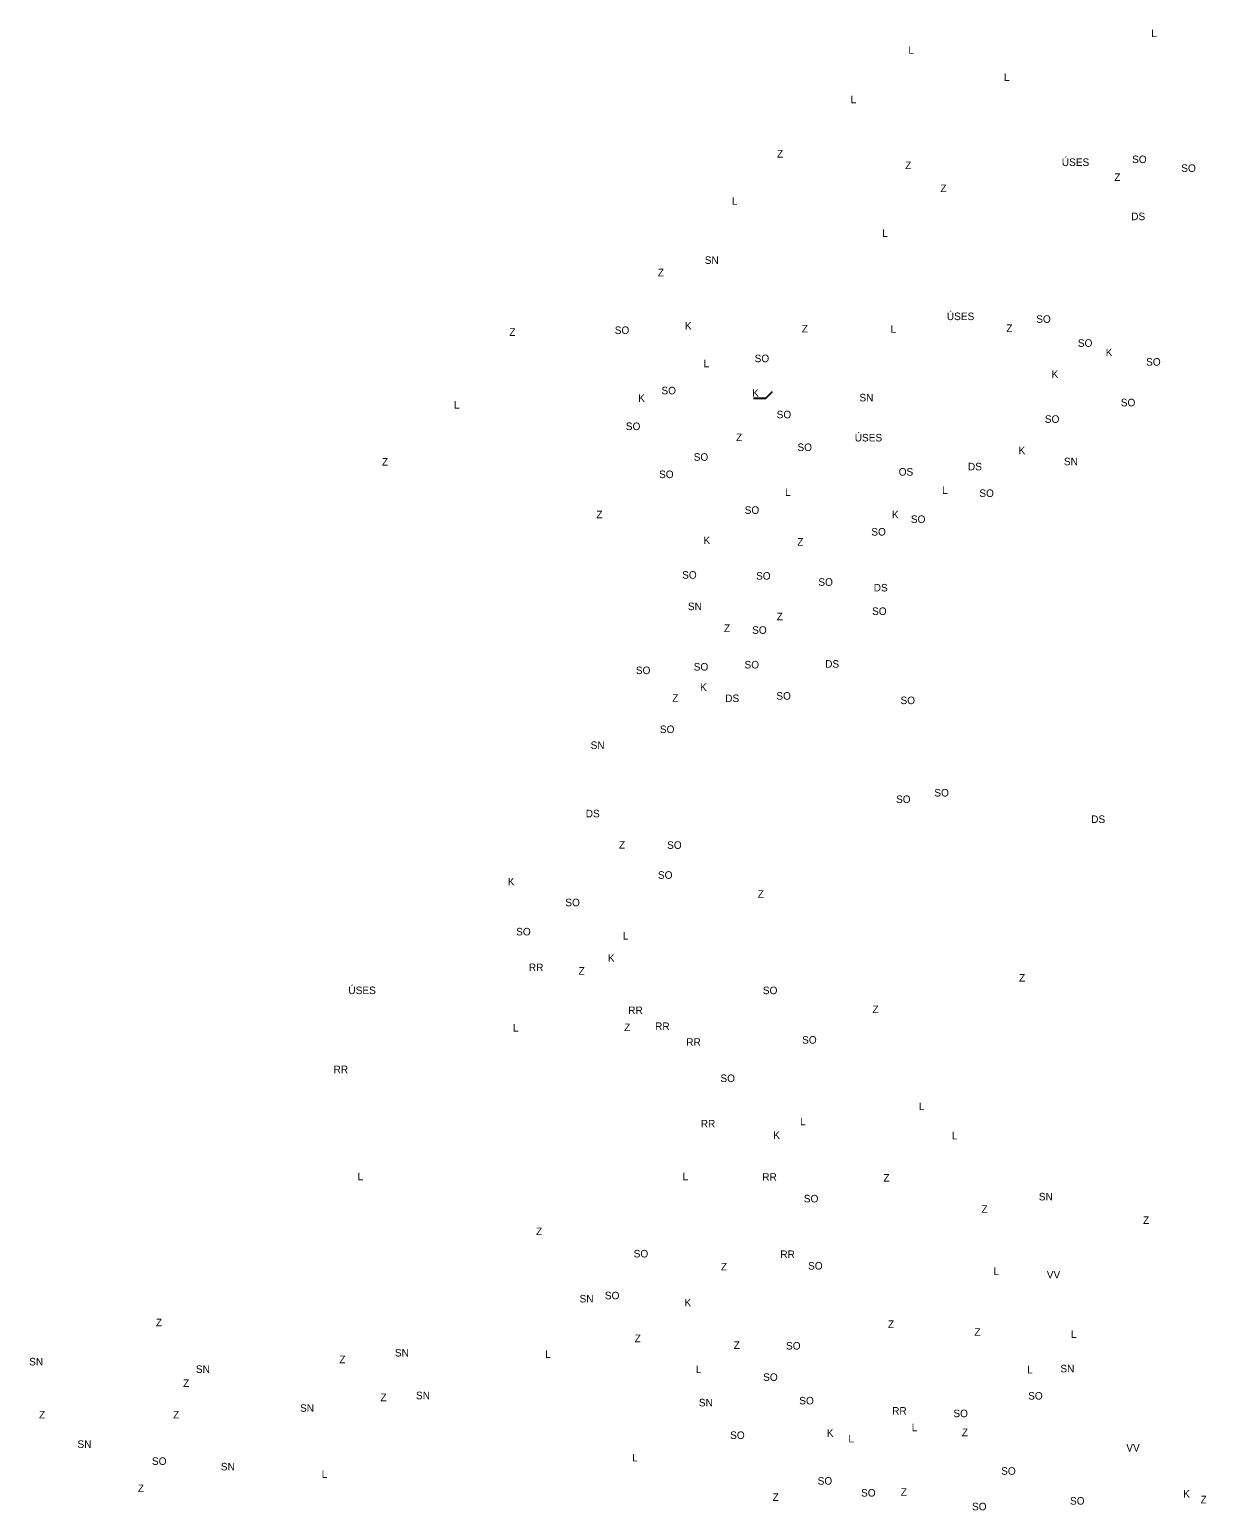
# Model space of a CAD drawing. Extents: x -445021 to -431236, y -1134464 to -1129615.
# Drawn here: x -443696 to -442135, y -1132159 to -1130195 of the extents above; entities that cross this region are included whole.
import ezdxf

# ---------------------------------------------------------------- set-up
doc = ezdxf.new("R2010")
doc.units = 0
doc.layers.add('Vrstva 4', color=7, linetype='Continuous')

msp = doc.modelspace()

# ---------------------------------------------------------------- linework, layer by layer
at = {"layer": 'Vrstva 4'}
msp.add_lwpolyline([(-442736, -1130683.7), (-442719.4, -1130683.7), (-442710.7, -1130675.1)], dxfattribs=at)

# ---------------------------------------------------------------- texts
for s, p in [('L', (-442208, -1130205.1)), ('L', (-442530.3, -1130227.2)), ('L', (-442403.5, -1130263.1)), ('L', (-442606.9, -1130292.7)), ('Z', (-442704.6, -1130364.7)), ('Z', (-442534.6, -1130380)), ('ÚSES', (-442326.8, -1130375.9)), ('SO', (-442233.5, -1130372.1)), ('SO', (-442168.3, -1130383.8)), ('Z', (-442257.1, -1130395.8)), ('Z', (-442487.8, -1130410.5)), ('L', (-442764.5, -1130427.3)), ('DS', (-442234.7, -1130447.8)), ('L', (-442565.1, -1130469.9)), ('SN', (-442800.5, -1130505.7)), ('Z', (-442862.7, -1130522.3)), ('ÚSES', (-442479.3, -1130580.3)), ('SO', (-442919.9, -1130598.7)), ('K', (-442826.9, -1130592.8)), ('Z', (-442671.7, -1130596.6)), ('L', (-442553.9, -1130597.1)), ('Z', (-442400.4, -1130596.1)), ('SO', (-442360.7, -1130583.9)), ('Z', (-443059.8, -1130601.2)), ('SO', (-442305.5, -1130615.7)), ('SO', (-442734.3, -1130636.1)), ('K', (-442268.5, -1130628.1)), ('L', (-442802, -1130642.8)), ('K', (-442340.3, -1130656.9)), ('SO', (-442214.9, -1130640.7)), ('SO', (-442857.9, -1130678.7)), ('L', (-443133.2, -1130697.6)), ('K', (-442888.8, -1130688.8)), ('K', (-442737.6, -1130681.9)), ('SN', (-442595.3, -1130688.1)), ('SO', (-442248.5, -1130694.6)), ('SO', (-442705.1, -1130710.5)), ('SO', (-442349.3, -1130716.5)), ('SO', (-442905.2, -1130726.1)), ('Z', (-442758.9, -1130740.7)), ('SO', (-442677.5, -1130753.9)), ('ÚSES', (-442601.5, -1130741.2)), ('Z', (-443228.8, -1130773.3)), ('SO', (-442815.1, -1130766.8)), ('K', (-442384.2, -1130758.1)), ('SN', (-442324, -1130772.8)), ('SO', (-442861.1, -1130789.8)), ('OS', (-442543.2, -1130786.5)), ('DS', (-442451.3, -1130779.5)), ('L', (-442694, -1130813.5)), ('L', (-442485.7, -1130810.8)), ('SO', (-442436.2, -1130814.8)), ('Z', (-442944.2, -1130843)), ('SO', (-442747.5, -1130837.2)), ('K', (-442552.1, -1130843.1)), ('SO', (-442527, -1130849.3)), ('SO', (-442579.5, -1130866)), ('K', (-442802.1, -1130877.3)), ('Z', (-442677.7, -1130879.4)), ('SO', (-442830.5, -1130923.2)), ('SO', (-442732.4, -1130924.4)), ('SO', (-442649.8, -1130932.6)), ('DS', (-442576.3, -1130940.1)), ('SN', (-442822.9, -1130964.9)), ('SO', (-442578.5, -1130971.3)), ('Z', (-442705, -1130978.3)), ('Z', (-442775, -1130993.9)), ('SO', (-442737.6, -1130996.3)), ('SO', (-442891.9, -1131049.7)), ('SO', (-442815.1, -1131045)), ('SO', (-442747.7, -1131042.2)), ('DS', (-442640.7, -1131041.2)), ('Z', (-442843.6, -1131086.4)), ('K', (-442806.7, -1131072)), ('DS', (-442773.4, -1131086.8)), ('SO', (-442705.5, -1131083.6)), ('SO', (-442540.8, -1131089.5)), ('SO', (-442860, -1131127.9)), ('SN', (-442951.9, -1131149)), ('SO', (-442546.7, -1131220.6)), ('SO', (-442495.9, -1131212)), ('DS', (-442958.4, -1131239.6)), ('DS', (-442287.8, -1131247.1)), ('Z', (-442914.3, -1131281)), ('SO', (-442850.4, -1131281.4)), ('SO', (-442862.6, -1131321.1)), ('K', (-443061.8, -1131329.9)), ('Z', (-442730.2, -1131346.3)), ('SO', (-442985.5, -1131357.5)), ('SO', (-443050.7, -1131396.2)), ('L', (-442909.1, -1131401.8)), ('RR', (-443033.8, -1131443.6)), ('K', (-442929, -1131431.1)), ('Z', (-442967.9, -1131448.3)), ('Z', (-442383.5, -1131457.5)), ('ÚSES', (-443273.3, -1131474)), ('SO', (-442723.4, -1131474.1)), ('RR', (-442902, -1131500.5)), ('Z', (-442578, -1131499.2)), ('RR', (-442866.4, -1131521.6)), ('L', (-443054.9, -1131523.7)), ('Z', (-442907.4, -1131523.1)), ('RR', (-442825, -1131542.6)), ('SO', (-442671.3, -1131539.7)), ('RR', (-443293, -1131578.9)), ('SO', (-442779.7, -1131590.6)), ('L', (-442516.5, -1131627.9)), ('RR', (-442805.8, -1131650.9)), ('L', (-442674.1, -1131648)), ('K', (-442709.6, -1131666)), ('L', (-442472.7, -1131666.6)), ('L', (-443261.1, -1131720.8)), ('L', (-442829.9, -1131720.8)), ('RR', (-442724.2, -1131721.5)), ('Z', (-442563.4, -1131722.6)), ('SO', (-442669, -1131750.2)), ('SN', (-442357.3, -1131747.6)), ('Z', (-442433.4, -1131764)), ('Z', (-443024.4, -1131793.6)), ('Z', (-442219, -1131778.8)), ('SO', (-442894.8, -1131823.2)), ('RR', (-442700.2, -1131824)), ('Z', (-442779, -1131840.4)), ('SO', (-442663.4, -1131839.3)), ('L', (-442417.5, -1131846.5)), ('VV', (-442346.7, -1131851)), ('SN', (-442966.6, -1131882.9)), ('SO', (-442933, -1131878.7)), ('K', (-442827.3, -1131888.1)), ('Z', (-443528.7, -1131914.5)), ('Z', (-442557.5, -1131916.8)), ('Z', (-442442.7, -1131927)), ('L', (-442314.7, -1131930)), ('SN', (-443211.6, -1131954.6)), ('Z', (-442893.5, -1131935.6)), ('Z', (-442762, -1131944.5)), ('SO', (-442692.7, -1131945.3)), ('SN', (-443696.8, -1131966.4)), ('Z', (-443285.3, -1131963.4)), ('L', (-443012.2, -1131956.5)), ('SN', (-443475.6, -1131976.3)), ('L', (-442812.3, -1131976.6)), ('SO', (-442723, -1131986.9)), ('L', (-442372.7, -1131976.9)), ('SN', (-442328.7, -1131975.6)), ('Z', (-443492.5, -1131994.9)), ('Z', (-443230.8, -1132013.8)), ('SN', (-443183.6, -1132011.2)), ('SO', (-442371.4, -1132011.7)), ('SN', (-443337.4, -1132027.9)), ('SN', (-442808.3, -1132020.7)), ('SO', (-442675.1, -1132018.1)), ('RR', (-442551.9, -1132031.6)), ('Z', (-443683.7, -1132036.7)), ('Z', (-443505.8, -1132036.7)), ('SO', (-442470.6, -1132035)), ('SO', (-442766.8, -1132063.9)), ('K', (-442638.6, -1132061.1)), ('L', (-442609.9, -1132068.5)), ('L', (-442525.9, -1132053.7)), ('Z', (-442459.4, -1132060.2)), ('SN', (-443632.7, -1132075.8)), ('VV', (-442241.2, -1132080.6)), ('SO', (-443533.9, -1132098.3)), ('SN', (-443442.5, -1132105.6)), ('L', (-442896.8, -1132093.7)), ('SO', (-442407.2, -1132111.4)), ('L', (-443308.7, -1132115.6)), ('SO', (-442650.7, -1132124.5)), ('Z', (-443552.6, -1132134.4)), ('Z', (-442710.5, -1132146.1)), ('SO', (-442593.1, -1132140.3)), ('Z', (-442540.5, -1132139.3)), ('SO', (-442315.9, -1132151)), ('K', (-442165.8, -1132141.6)), ('Z', (-442142.7, -1132149.3)), ('SO', (-442445.9, -1132158.5))]:
    msp.add_text(s, height=10, dxfattribs=at).set_placement(p)

doc.saveas('drawing.dxf')
